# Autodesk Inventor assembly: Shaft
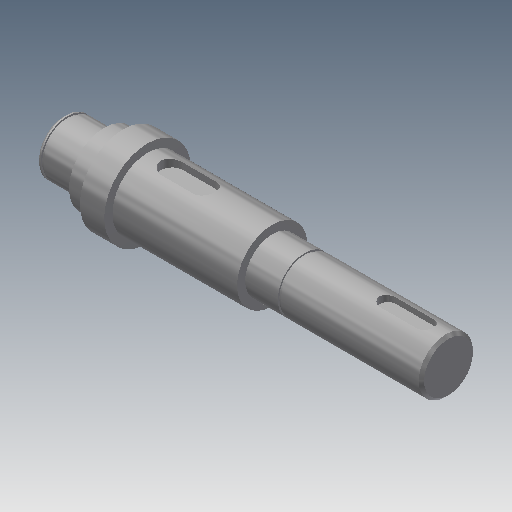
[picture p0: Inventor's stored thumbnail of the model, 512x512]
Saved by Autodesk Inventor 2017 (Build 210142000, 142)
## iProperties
Created: 2019-02
Part Number: Shaft
Document SubType Name: Assembly
Designer: user
ClientObjectVersion: 1
Author: user
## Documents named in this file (2)
- C:\Users\user\Documents\EIA\Cursos\Diseño asistido por computador\Clase 7 Dynamic simulation\Ensamble reductor de velocidad\Ensamble\Design Accelerator\Shaft2.iam
- C:\Users\user\Documents\EIA\Cursos\Diseño asistido por computador\Clase 7 Dynamic simulation\Ensamble reductor de velocidad\Ensamble\Design Accelerator\Shaft2.ipt
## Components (1 placed, 1 different names)
1. Shaft:1
